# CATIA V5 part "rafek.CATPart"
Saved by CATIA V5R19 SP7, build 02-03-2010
Part number: rafek
Bounding box of the stored display mesh (mm): x 0 to 0, y -100 to 100, z 0 to 30
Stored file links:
  C:\DURATEC\Software\CATIA\CATIA forum\rafek.CATPart
  C:\DURATEC\Software\CATIA\CATIA forum\rafek.xls
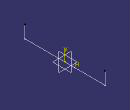
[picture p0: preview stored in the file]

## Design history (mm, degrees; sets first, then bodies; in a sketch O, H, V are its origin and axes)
Parameters
  `Vyber rozmer` = "middle"
  rozmer = "middle" {design table}
  sirka_rafku = 200 mm {design table}
Body1 (main body)
  Sketch1 on yz-plane, origin (0, 0, 0), H (0, 1, 0), V (0, 0, 1)
    line L1 (-100, 0) -> (100, 0)
    line L2 (-100, 0) -> (-100, 30)
    construction line L3 (-100, 30) -> (100, 30)
    line L4 (100, 30) -> (100, 0)
    length L4 = 30
    length L3 = 200 {= sirka_rafku}
    midpoint: L1 O
    horizontal: L1 H, L3 H
    vertical: L2 V, L4 V
Relations
  design table, configuration 2, drives sirka_rafku, rozmer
